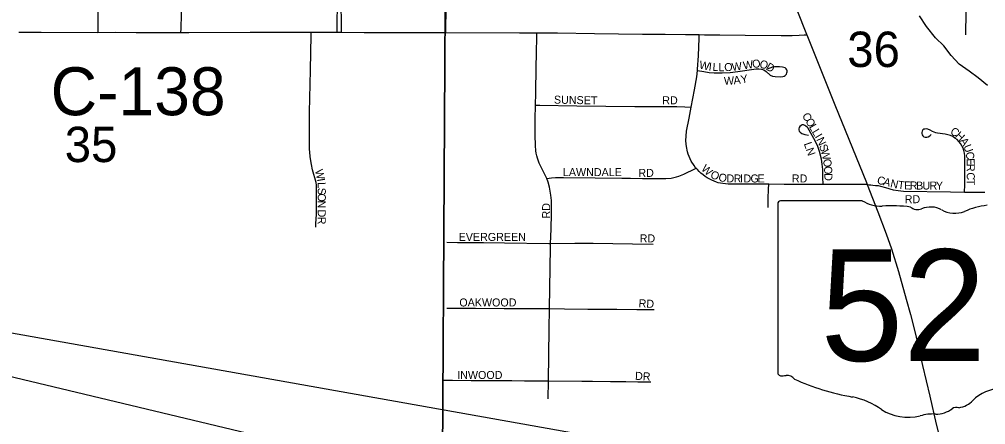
# Model space of a CAD drawing. Extents: x -9.1 to 34, y -3.1 to 22.
# Drawn here: x 6.722 to 7.865, y 17.795 to 18.275 of the extents above; entities that cross this region are included whole.
import ezdxf

# ---------------------------------------------------------------- set-up
doc = ezdxf.new("R2010")
doc.units = 0
for name, color, linetype in [('GM_X_City_Street', 7, 'Continuous'), ('GM_X_Corporation', 7, 'Continuous'), ('GM_X_County_Road', 7, 'Continuous'), ('GM_X_County_Road_Text', 7, 'Continuous'), ('GM_X_Minor_River', 7, 'Continuous'), ('GM_X_Section', 7, 'Continuous'), ('GM_X_Section_Text', 7, 'Continuous'), ('GM_X_State_Location', 7, 'Continuous'), ('GM_X_State_Route', 7, 'Continuous'), ('GM_X_State_Shield', 7, 'Continuous'), ('GM_X_Township_Subdivision', 7, 'Continuous'), ('GM_X_Township_Subdivision_Text', 7, 'Continuous'), ('SH_Text', 7, 'Continuous')]:
    doc.layers.add(name, color=color, linetype=linetype)

msp = doc.modelspace()

# ---------------------------------------------------------------- linework, layer by layer
at = {"layer": 'GM_X_City_Street'}
for points in [[(6.9133, 18.2594), (6.9134, 18.2637), (6.9139, 18.2811), (6.914, 18.3029), (6.9145, 18.3302)], [(7.0979, 18.2596), (7.098, 18.2663), (7.098, 18.2788), (7.0986, 18.2834), (7.0991, 18.2858), (7.0999, 18.2883), (7.1011, 18.2907)], [(7.1032, 18.2596), (7.1033, 18.2659), (7.1033, 18.2796), (7.1029, 18.2835), (7.1025, 18.2859), (7.102, 18.2882), (7.1011, 18.2907)]]:
    msp.add_lwpolyline(points, dxfattribs=at)
at = {"layer": 'GM_X_Corporation'}
msp.add_lwpolyline([(6.7215, 18.3948), (6.8153, 18.395), (6.8149, 18.2595), (7.0673, 18.2597), (7.2265, 18.2595), (7.2308, 18.6038), (7.233, 18.7587), (6.9788, 18.7597), (6.9804, 18.8331), (7.012, 18.8334), (7.0128, 18.8143), (7.0487, 18.8146), (7.0492, 18.9061), (7.0496, 18.9852), (7.0158, 19.0041), (6.9933, 19.0167), (6.984, 19.0235), (6.9856, 19.3076)], dxfattribs=at)
at = {"layer": 'GM_X_County_Road'}
for points in [[(6.7215, 18.2599), (6.7295, 18.2596), (6.7478, 18.2597), (6.8149, 18.2595)], [(6.8149, 18.2595), (6.8356, 18.2597), (6.8605, 18.2594), (6.9133, 18.2594)], [(6.9133, 18.2594), (6.9227, 18.2594), (6.9952, 18.2596), (7.0673, 18.2597)], [(7.0673, 18.2597), (7.072, 18.2597), (7.0979, 18.2596)], [(7.0979, 18.2596), (7.1032, 18.2596)], [(7.1032, 18.2596), (7.1298, 18.2595), (7.1854, 18.2595), (7.2151, 18.2594), (7.2265, 18.2595)], [(7.2265, 18.2595), (7.3138, 18.2588), (7.334, 18.2588)], [(7.334, 18.2588), (7.3586, 18.2588), (7.4025, 18.2583), (7.4593, 18.2575), (7.486, 18.2573), (7.51, 18.257), (7.5261, 18.2568)], [(7.5261, 18.2568), (7.5325, 18.2567), (7.5504, 18.2565), (7.5805, 18.2562), (7.6231, 18.2557), (7.636, 18.2557), (7.6446, 18.256), (7.6503, 18.2564), (7.6534, 18.2567)]]:
    msp.add_lwpolyline(points, dxfattribs=at)
at = {"layer": 'GM_X_Minor_River'}
msp.add_lwpolyline([(7.867, 18.1967), (7.8561, 18.2058), (7.8455, 18.2135), (7.8338, 18.2218), (7.8243, 18.2321), (7.8153, 18.2435), (7.8058, 18.253), (7.7949, 18.2663), (7.7866, 18.2789)], dxfattribs=at)
at = {"layer": 'GM_X_Section'}
for points in [[(6.2253, 18.7649), (7.2285, 18.7534), (7.2227, 17.7567), (6.224, 17.7617)], [(7.2285, 18.7534), (8.2465, 18.7547), (8.2334, 17.7485), (7.2227, 17.7567)]]:
    msp.add_lwpolyline(points, close=True, dxfattribs=at)
at = {"layer": 'GM_X_State_Route'}
for points in [[(7.6415, 18.2863), (7.6531, 18.2575), (7.6534, 18.2567)], [(7.6534, 18.2567), (7.6715, 18.2113), (7.6867, 18.1739), (7.7239, 18.0818), (7.7249, 18.0793), (7.7376, 18.0471), (7.7474, 18.021), (7.7536, 18.0034), (7.7617, 17.9766), (7.771, 17.9437), (7.7759, 17.9257), (7.7819, 17.9023), (7.7866, 17.8812), (7.7902, 17.8654), (7.7945, 17.8473), (7.7988, 17.8291), (7.8065, 17.7959), (7.8102, 17.7807)]]:
    msp.add_lwpolyline(points, dxfattribs=at)
at = {"layer": 'GM_X_State_Shield'}
for p, q in [((7.7189, 18.0603), (7.6224, 18.0603)), ((7.6192, 18.0568), (7.6192, 17.8567))]:
    msp.add_line(p, q, dxfattribs=at)
for centre, major_axis, start_param, end_param in [((7.6229, 18.0572), (0.00382, 0), 1.712693, 3.28349), ((7.7419, 18.0835), (0.037, 0), 4.042523, 4.731795), ((7.7542, 17.9479), (0.133, 0), 1.404758, 1.657858), ((7.7844, 18.0583), (0.0107, 0), 3.836095, 5.185415), ((7.8, 18.0351), (0.0222, 0), 0.950623, 2.079405), ((7.8287, 18.0669), (0.0267, 0), 4.081561, 5.145723), ((7.8759, 17.9991), (0.0703, 0), 1.699011, 2.107814), ((7.623, 17.8563), (0.00385, 0), 3.00124, 4.508301), ((7.6235, 17.8767), (0.0294, 0), 4.665946, 4.897461), ((7.6296, 17.8451), (0.0106, 0), 0.519207, 1.627899), ((7.7634, 18.0249), (0.2524, 0), 4.195997, 4.488961), ((7.8878, 17.8005), (0.0479, 0), 1.647645, 2.488434), ((7.6881, 17.7668), (0.079, 0), 0.823519, 1.323587), ((7.8271, 17.8373), (0.0282, 0), 4.937069, 5.64225), ((7.7735, 17.8442), (0.0501, 0), 4.026481, 4.996735), ((7.8025, 17.775), (0.0412, 0), 1.495662, 1.94098), ((7.8062, 17.8292), (0.0267, 0), 4.691044, 5.507374), ((7.8303, 17.8098), (0.00752, 0), 1.147584, 2.315152)]:
    msp.add_ellipse(centre, major_axis=major_axis, ratio=0.8, start_param=start_param, end_param=end_param, dxfattribs=at)
at = {"layer": 'GM_X_Township_Subdivision'}
for points in [[(7.8416, 18.2564), (7.8415, 18.2628), (7.8425, 18.3071)], [(7.066, 18.113), (7.0654, 18.1215), (7.0652, 18.1339), (7.0652, 18.1651), (7.0664, 18.2149), (7.0672, 18.2562), (7.0673, 18.2597)], [(7.3326, 18.1733), (7.3329, 18.1876), (7.3333, 18.2187), (7.3336, 18.2342), (7.334, 18.2555), (7.334, 18.2588)], [(7.5241, 18.2145), (7.5243, 18.2161), (7.5252, 18.2317), (7.526, 18.2528), (7.5261, 18.2568)], [(7.5241, 18.2145), (7.5316, 18.2132), (7.5378, 18.2122), (7.544, 18.2117), (7.5534, 18.2115), (7.5627, 18.212), (7.572, 18.213), (7.5937, 18.2163), (7.5968, 18.2164), (7.5999, 18.2161), (7.6028, 18.215), (7.6053, 18.2132), (7.61, 18.209), (7.6128, 18.2077), (7.6159, 18.2072), (7.6221, 18.207), (7.6252, 18.2074), (7.6267, 18.2077), (7.628, 18.2084), (7.6288, 18.2092), (7.6295, 18.2102), (7.6299, 18.2115), (7.6301, 18.2127), (7.6301, 18.2139), (7.6298, 18.2151), (7.6289, 18.2163), (7.6278, 18.2174), (7.6263, 18.2179), (7.6245, 18.2183), (7.6212, 18.2186), (7.617, 18.2188), (7.6151, 18.2187), (7.614, 18.2185), (7.6126, 18.2182), (7.6108, 18.2177), (7.6075, 18.2164)], [(7.5168, 18.1711), (7.5208, 18.1914), (7.5233, 18.2068), (7.5241, 18.2145)], [(7.346, 18.0864), (7.3453, 18.0882), (7.3371, 18.1049), (7.3348, 18.1106), (7.334, 18.1135), (7.3333, 18.1165), (7.3329, 18.1195), (7.3324, 18.1256), (7.332, 18.138), (7.3323, 18.1566), (7.3326, 18.1733)], [(7.3326, 18.1733), (7.3377, 18.1733), (7.3813, 18.1727), (7.4499, 18.1717), (7.4778, 18.1718)], [(7.4778, 18.1718), (7.481, 18.1718), (7.4996, 18.1718), (7.509, 18.1714), (7.5168, 18.1711)], [(7.5224, 18.0989), (7.522, 18.0994), (7.5202, 18.1019), (7.5168, 18.107), (7.5154, 18.1097), (7.5142, 18.1125), (7.5131, 18.1153), (7.5123, 18.1183), (7.511, 18.1243), (7.5106, 18.1273), (7.5104, 18.1316), (7.5106, 18.1365), (7.5113, 18.1426), (7.5142, 18.1578), (7.5168, 18.1711)], [(7.6727, 18.0795), (7.6725, 18.088), (7.6723, 18.0973), (7.6717, 18.1035), (7.6707, 18.1096), (7.6684, 18.1187), (7.6664, 18.1246), (7.6638, 18.1302), (7.6562, 18.1438), (7.6546, 18.1465), (7.6537, 18.1475), (7.6524, 18.1487), (7.6512, 18.1494), (7.6496, 18.1499), (7.6479, 18.1499), (7.6466, 18.1494), (7.6453, 18.1483), (7.6445, 18.1471), (7.644, 18.1453), (7.6441, 18.1441), (7.6446, 18.1425), (7.6454, 18.1413), (7.6477, 18.1397), (7.6511, 18.1385), (7.6553, 18.1377)], [(7.8401, 18.0706), (7.8402, 18.0792), (7.8405, 18.1103), (7.8404, 18.1135), (7.8401, 18.1165), (7.8393, 18.1196), (7.8382, 18.1225), (7.8369, 18.1253), (7.8353, 18.128), (7.8334, 18.1304), (7.8312, 18.1326), (7.8287, 18.1345), (7.826, 18.1361), (7.8232, 18.1374), (7.8203, 18.1384), (7.8172, 18.1391), (7.808, 18.1401), (7.806, 18.1405), (7.804, 18.1414), (7.8021, 18.1423), (7.7994, 18.1439), (7.7965, 18.1451), (7.7945, 18.1453), (7.7932, 18.1451), (7.7919, 18.1448), (7.7908, 18.144), (7.7897, 18.1427), (7.7893, 18.1412), (7.7894, 18.1397), (7.7897, 18.1382), (7.7906, 18.137), (7.7918, 18.136), (7.7934, 18.1355), (7.7952, 18.1355), (7.7969, 18.1359), (7.7988, 18.137), (7.8007, 18.1388)], [(7.0726, 18.029), (7.0728, 18.0332), (7.0732, 18.0383), (7.0735, 18.0445), (7.0737, 18.0663), (7.0735, 18.0788), (7.0731, 18.0819), (7.069, 18.0969), (7.0676, 18.103), (7.0661, 18.1122), (7.066, 18.113)], [(7.4759, 18.0865), (7.4807, 18.0865), (7.4866, 18.0865), (7.4931, 18.0871), (7.4992, 18.0884), (7.5022, 18.0893), (7.5079, 18.0916), (7.5136, 18.0943), (7.5163, 18.0957), (7.5224, 18.0989)], [(7.6085, 18.0797), (7.5975, 18.0797), (7.5747, 18.0798), (7.5603, 18.0799), (7.5541, 18.0805), (7.5512, 18.081), (7.5488, 18.0816), (7.5466, 18.0824), (7.544, 18.0835), (7.5411, 18.0846), (7.5357, 18.0874), (7.5331, 18.089), (7.5307, 18.0908), (7.5283, 18.0928), (7.5261, 18.0949), (7.524, 18.0971), (7.5224, 18.0989)], [(7.346, 18.0864), (7.3514, 18.0873), (7.3564, 18.0876), (7.3658, 18.0878), (7.4032, 18.0875), (7.4345, 18.0871), (7.445, 18.0869), (7.4593, 18.0867), (7.4759, 18.0865)], [(7.3505, 18.0098), (7.351, 18.0265), (7.3514, 18.0451), (7.3514, 18.0607), (7.3508, 18.067), (7.3492, 18.0762), (7.3476, 18.0823), (7.346, 18.0864)], [(7.6076, 18.0521), (7.6079, 18.0631), (7.6083, 18.0738), (7.6085, 18.0797)], [(7.6727, 18.0795), (7.6646, 18.0795), (7.6431, 18.0796), (7.6268, 18.0796), (7.6085, 18.0797)], [(7.7249, 18.0793), (7.6819, 18.0794), (7.6727, 18.0795)], [(7.7249, 18.0793), (7.7257, 18.0793), (7.7272, 18.0791), (7.7292, 18.079), (7.7315, 18.0788), (7.7346, 18.0785), (7.7377, 18.0782), (7.7407, 18.0777), (7.7467, 18.076), (7.7555, 18.0733), (7.7616, 18.0723), (7.7677, 18.0717), (7.8232, 18.0708), (7.8401, 18.0706)], [(7.8401, 18.0706), (7.8571, 18.0704), (7.8639, 18.0704)], [(7.2278, 18.0114), (7.2402, 18.0109), (7.2711, 18.0107), (7.2958, 18.0106), (7.3482, 18.0098), (7.3505, 18.0098)], [(7.3491, 17.9326), (7.3504, 18.0048), (7.3505, 18.0098)], [(7.3505, 18.0098), (7.3791, 18.0099), (7.4007, 18.0099), (7.4471, 18.0094), (7.4719, 18.0089)], [(7.2278, 17.9331), (7.2401, 17.9332), (7.2617, 17.933), (7.2957, 17.9329), (7.3328, 17.9327), (7.3491, 17.9326)], [(7.3478, 17.8472), (7.3487, 17.9085), (7.3491, 17.9326)], [(7.3491, 17.9326), (7.3667, 17.9325), (7.3946, 17.9321), (7.4286, 17.9318), (7.4526, 17.9316), (7.4625, 17.9315), (7.4692, 17.9315), (7.473, 17.9314)], [(7.2241, 17.8479), (7.2344, 17.8479), (7.2563, 17.8477), (7.2673, 17.8477), (7.2852, 17.8475), (7.3045, 17.8474), (7.3196, 17.8473), (7.3473, 17.8472), (7.3478, 17.8472)], [(7.3474, 17.8259), (7.3478, 17.8472)], [(7.3478, 17.8472), (7.3875, 17.8469), (7.3998, 17.8467), (7.4211, 17.8465), (7.4281, 17.8464), (7.4395, 17.8463), (7.4538, 17.8462), (7.4552, 17.8462), (7.4648, 17.8461), (7.4691, 17.8461)]]:
    msp.add_lwpolyline(points, dxfattribs=at)
at = {"layer": 'SH_Text'}
msp.add_lwpolyline([(9.7227, 17.3677), (5.8733, 18.0531), (9.7227, 17.1316)], close=True, dxfattribs=at)

# ---------------------------------------------------------------- texts
at = {"layer": 'GM_X_County_Road_Text'}
msp.add_text('C-138', height=0.05682, rotation=0, dxfattribs=at).set_placement((6.7592, 18.1614))
at = {"layer": 'GM_X_Section_Text'}
for s, p in [('36', (7.7013, 18.2185)), ('35', (6.7758, 18.106))]:
    msp.add_text(s, height=0.04186, rotation=0, dxfattribs=at).set_placement(p)
at = {"layer": 'GM_X_State_Location'}
for s in ['s', 'r']:
    msp.add_text(s, height=0.000189, dxfattribs=at).set_placement((7.7719, 17.9183))
msp.add_text('529', height=0.000189, rotation=0, dxfattribs=at).set_placement((7.705, 17.9045))
at = {"layer": 'GM_X_State_Shield'}
msp.add_text('529', height=0.13184, dxfattribs=at).set_placement((7.6695, 17.8708))
at = {"layer": 'GM_X_Township_Subdivision_Text'}
for s, rotation, p in [('W', 348.6439, (7.5256, 18.2168)), ('I', 353.3167, (7.537, 18.2145)), ('L', 356.7721, (7.5418, 18.214)), ('L', 359.6443, (7.5489, 18.2136)), ('O', 1.4686, (7.5559, 18.2136)), ('W', 6.5688, (7.5652, 18.2138)), ('W', 8.8539, (7.5788, 18.2155)), ('O', 6.7481, (7.5894, 18.2172)), ('O', 343.6734, (7.5967, 18.2182)), ('D', 329.9135, (7.6042, 18.2161)), ('W', 3.1957, (7.5557, 18.1973)), ('A', 6.4477, (7.5672, 18.1979)), ('Y', 10.5554, (7.5762, 18.199)), ('SUNSET', 358.9165, (7.3543, 18.1752)), ('RD', 0, (7.4825, 18.1744)), ('C', 301.2845, (7.6474, 18.161)), ('O', 301.2824, (7.6513, 18.1546)), ('L', 301.3072, (7.6556, 18.1475)), ('L', 301.2871, (7.659, 18.1418)), ('I', 301.2637, (7.6625, 18.1361)), ('C', 327.6033, (7.8222, 18.1401)), ('H', 316.7469, (7.8282, 18.1364)), ('LN', 289.1749, (7.6498, 18.1278)), ('N', 295.0499, (7.6645, 18.1328)), ('S', 287.1389, (7.6679, 18.1256)), ('A', 304.6965, (7.8339, 18.1311)), ('U', 290.5919, (7.8384, 18.1248)), ('W', 284.4278, (7.6699, 18.1193)), ('C', 279.4424, (7.8412, 18.1175)), ('W', 317.5691, (7.5278, 18.0971)), ('O', 278.5351, (7.6725, 18.1091)), ('E', 271.667, (7.8424, 18.1104)), ('R', 270.2915, (7.8426, 18.1038)), ('W', 282.9883, (7.0717, 18.0963)), ('LAWNDALE', 0, (7.365, 18.0894)), ('RD', 0, (7.4542, 18.0885)), ('O', 335.6373, (7.5385, 18.088)), ('O', 348.2227, (7.5483, 18.0839)), ('D', 359.4296, (7.5584, 18.082)), ('R', 359.9941, (7.5669, 18.0819)), ('I', 0, (7.5744, 18.0819)), ('D', 0, (7.5785, 18.0819)), ('G', 0, (7.5869, 18.0819)), ('E', 0, (7.5952, 18.0819)), ('RD', 0, (7.6358, 18.0819)), ('O', 273.3896, (7.6737, 18.101)), ('D', 270.4372, (7.6742, 18.0929)), ('C', 269.994, (7.8426, 18.0938)), ('I', 279.4408, (7.0741, 18.0859)), ('L', 272.6782, (7.0748, 18.0821)), ('C', 343.7544, (7.7357, 18.0809)), ('A', 345.096, (7.7431, 18.0788)), ('N', 347.7414, (7.7516, 18.0765)), ('T', 353.039, (7.7607, 18.0746)), ('E', 358.8648, (7.7684, 18.0737)), ('R', 359.8516, (7.7752, 18.0736)), ('B', 359.9941, (7.7827, 18.0735)), ('U', 359.9929, (7.7902, 18.0735)), ('R', 359.9941, (7.7986, 18.0735)), ('Y', 359.9929, (7.8061, 18.0735)), ('T', 269.9956, (7.8426, 18.0863)), ('S', 270.1639, (7.0751, 18.0756)), ('O', 270, (7.0751, 18.0689)), ('N', 269.9928, (7.0751, 18.0606)), ('RD', 0, (7.7692, 18.0574)), ('D', 269.9928, (7.0751, 18.0498)), ('RD', 90, (7.3499, 18.0393)), ('R', 269.994, (7.0751, 18.0414)), ('EVERGREEN', 0, (7.2417, 18.0127)), ('RD', 0, (7.4558, 18.011)), ('OAKWOOD', 0, (7.2425, 17.9352)), ('RD', 356.8215, (7.4543, 17.9344)), ('INWOOD', 0, (7.24, 17.8494)), ('DR', 356.8215, (7.4501, 17.8485))]:
    msp.add_text(s, height=0.00947, rotation=rotation, dxfattribs=at).set_placement(p)

doc.saveas('drawing.dxf')
